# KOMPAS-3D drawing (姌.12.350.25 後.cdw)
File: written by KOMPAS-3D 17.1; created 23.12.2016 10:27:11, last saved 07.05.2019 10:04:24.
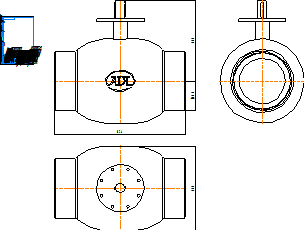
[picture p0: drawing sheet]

Sheet 1: A4, portrait

Title block, sheet 1: name: КШ.12.350.25 сс; material: Внимание! Данный продукт является объектом авторского права ООО «Торговый Дом АДЛ». / Запрещается изменение, копирование, распространение / (в том числе путем копирования на другие сайты и ресурсы в Интернете) / или любое иное использование информации и объектов без предварительного / согласия правообладателя (ООО «Торговый Дом АДЛ»).; sheets: 1; organisation: ООО "Торговый дом АДЛ"; sheet format: A4; stored path: C:\Users\tra\Desktop\2д чертежи\Шаровые краны БИВАЛ\КШ_Бивал_серия_11_12\KOMPAS_2D\КШ.12.350.25 сс.cdw

Views: Вид 1, Проекционный вид 2, Проекционный вид 3
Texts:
  Klimkovich
  ADL
Dimensions and other numbers on the sheet: 824; 505; 188,5; 530; 1:1; 1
